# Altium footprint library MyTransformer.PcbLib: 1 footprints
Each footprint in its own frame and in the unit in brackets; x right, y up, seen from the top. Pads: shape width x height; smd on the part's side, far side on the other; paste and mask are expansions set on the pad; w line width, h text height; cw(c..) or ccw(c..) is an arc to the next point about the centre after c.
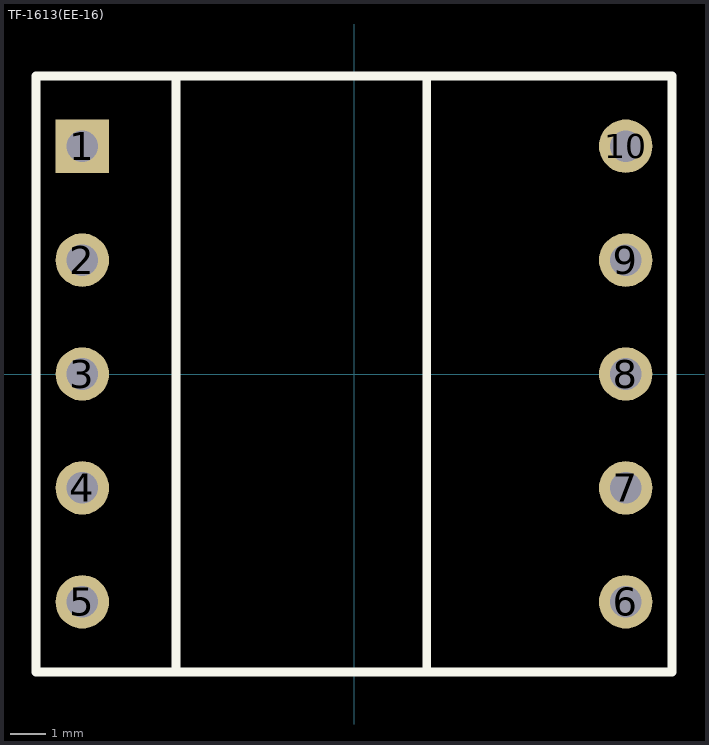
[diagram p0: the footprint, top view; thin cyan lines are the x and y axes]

## TF-1613(EE-16) [mm]
pads (10):
  rect 1.524x1.524 hole 0.9: 1(-7.75,6.5)
  round 1.524 hole 0.9: 2(-7.75,3.25) 3(-7.75,0) 4(-7.75,-3.25) 5(-7.75,-6.5) 6(7.75,-6.5) 7(7.75,-3.25) 8(7.75,0) 9(7.75,3.25) 10(7.75,6.5)
Top Overlay:
  lines w0.254: -5.05,8.5 2.1,8.5 ; -5,-8.5 2.15,-8.5 ; -9.075,-8.5 -5.075,-8.5 -5.075,8.5 -9.075,8.5 -9.075,-8.5 ; 2.075,-8.5 2.075,8.5 9.075,8.5 9.075,-8.5 2.075,-8.5
M5 Assembly Top:
  text ".Designator" at -1.524,-0.508 h1.02
3D body: height 4, standoff 0, extent -9.1,-8.5 9,8.5
3D body: height 10.96, standoff 1, extent -5.9,-4.9 6,5.08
